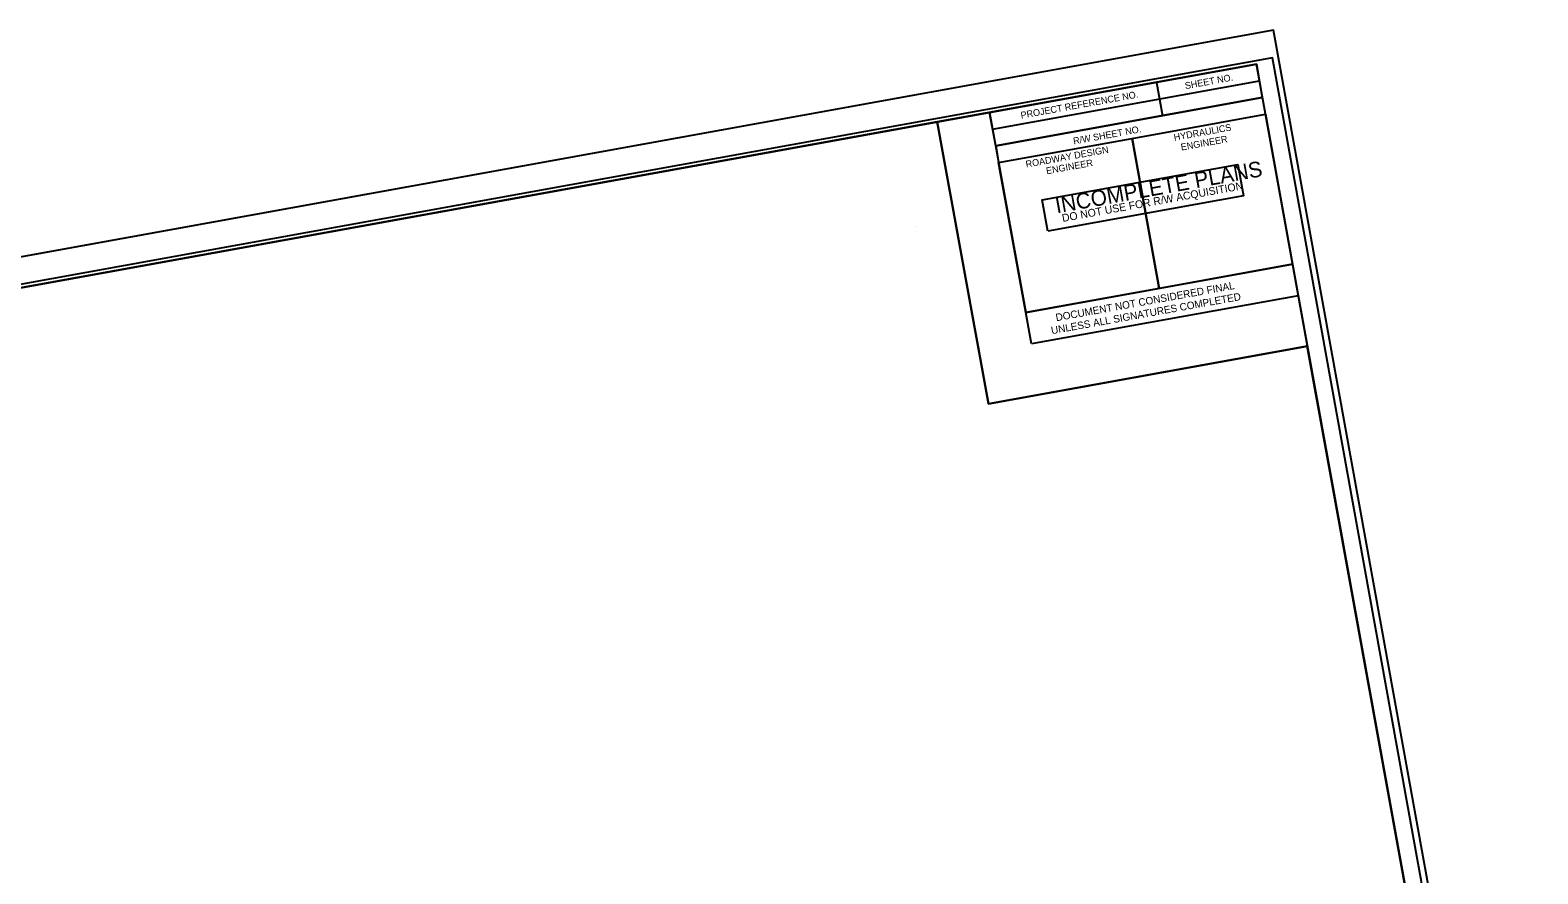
# Model space of a CAD drawing. Extents: x 1617779 to 1622406, y 896496 to 899510.
# Drawn here: x 1620890 to 1622002, y 898422 to 899045 of the extents above; entities that cross this region are included whole.
import ezdxf

# ---------------------------------------------------------------- set-up
doc = ezdxf.new("R2010")
doc.units = 0
for name, color, linetype in [('ControlPoints', 7, 'Continuous'), ('Exist Profile Cell', 7, 'Continuous'), ('Exist Vertical Profile Horizontal Axis Label Major', 7, 'Continuous'), ('Observations', 7, 'Continuous'), ('Prop Horizontal Alignment', 7, 'Continuous'), ('Prop Horizontal Alignment Curve and Spiral Data', 7, 'Continuous'), ('Scratch_Level_4', 7, 'Continuous'), ('Setups', 7, 'Continuous')]:
    doc.layers.add(name, color=color, linetype=linetype)

msp = doc.modelspace()

# ---------------------------------------------------------------- linework, layer by layer
at = {"layer": 'ControlPoints'}
msp.add_lwpolyline([(1620345.8, 897667.3), (1622002.3, 897967.2), (1621807.3, 899044.7), (1620150.7, 898744.8)], close=True, dxfattribs=at)
at = {"layer": 'Exist Profile Cell'}
for p, q in [((1621624.5, 898836.2), (1621821.3, 898871.9)), ((1621624.5, 898836.2), (1621821.3, 898871.9)), ((1621821.3, 898871.9), (1621825.5, 898848.7)), ((1621821.3, 898871.9), (1621825.5, 898848.7)), ((1621825.5, 898848.7), (1621628.7, 898813.1)), ((1621825.5, 898848.7), (1621628.7, 898813.1)), ((1621628.7, 898813.1), (1621624.5, 898836.2)), ((1621628.7, 898813.1), (1621624.5, 898836.2))]:
    msp.add_line(p, q, dxfattribs=at)
at = {"layer": 'Exist Vertical Profile Horizontal Axis Label Major'}
for p, q in [((1621599.9, 898971.5), (1621796.8, 899007.2)), ((1621720.8, 899006.1), (1621725.3, 898981.5)), ((1621602.2, 898959.2), (1621799, 898994.9)), ((1621602.2, 898959.2), (1621799, 898994.9)), ((1621702.9, 898964.7), (1621722.9, 898854.1)), ((1621602.2, 898959.2), (1621604.4, 898946.9))]:
    msp.add_line(p, q, dxfattribs=at)
for points in [[(1621794.6, 899019.5), (1620318.6, 898752.3), (1620505.6, 897719.1), (1621981.6, 897986.3)], [(1621597.7, 898983.9), (1621794.6, 899019.5), (1621799, 898994.9), (1621602.2, 898959.2)], [(1620505.6, 897719.1), (1620318.5, 898752.3), (1621597.7, 898983.9), (1621624.5, 898836.2), (1621821.3, 898871.9), (1621981.6, 897986.3)], [(1621702.9, 898964.7), (1621801.3, 898982.6), (1621821.3, 898871.9), (1621722.9, 898854)], [(1621604.4, 898946.9), (1621702.9, 898964.7), (1621722.9, 898854), (1621624.5, 898836.2)]]:
    msp.add_lwpolyline(points, close=True, dxfattribs=at)
at = {"layer": 'Observations'}
for points in [[(1621596.8, 898768.8), (1621832.3, 898811.4), (1621794.6, 899019.5), (1621559.1, 898976.9)], [(1620318.5, 898752.3), (1620505.6, 897719.1), (1621981.6, 897986.3), (1621832.2, 898811.4), (1621596.8, 898768.8), (1621559.1, 898976.9)]]:
    msp.add_lwpolyline(points, close=True, dxfattribs=at)
at = {"layer": 'Prop Horizontal Alignment'}
msp.add_line((1621807.3, 899044.7), (1620150.7, 898744.8), dxfattribs=at)
at = {"layer": 'Prop Horizontal Alignment Curve and Spiral Data'}
msp.add_lwpolyline([(1621640.6, 898896.3), (1621636.4, 898919.4), (1621781, 898945.6), (1621785.2, 898922.5)], close=True, dxfattribs=at)
at = {"layer": 'Scratch_Level_4'}
msp.add_line((1621543.7, 898900), (1621543.7, 898900), dxfattribs=at)
at = {"layer": 'Setups'}
msp.add_lwpolyline([(1620355, 897689.3), (1621994.3, 897986.1), (1621806.4, 899024.2), (1620167.1, 898727.5)], close=True, dxfattribs=at)

# ---------------------------------------------------------------- texts
at = {"layer": 'Exist Profile Cell'}
for s, p in [('DOCUMENT NOT CONSIDERED FINAL', (1621647, 898829.8)), ('DOCUMENT NOT CONSIDERED FINAL', (1621647, 898829.8)), ('UNLESS ALL SIGNATURES COMPLETED', (1621643.6, 898820.2)), ('UNLESS ALL SIGNATURES COMPLETED', (1621643.6, 898820.2))]:
    msp.add_text(s, height=5.5, rotation=10.2599, dxfattribs=at).set_placement(p)
at = {"layer": 'Exist Vertical Profile Horizontal Axis Label Major'}
for s, p in [('SHEET NO.', (1621742.3, 899001.1)), ('PROJECT REFERENCE NO.', (1621621.1, 898979.3)), ('R/W SHEET NO.', (1621659.9, 898960.3)), ('HYDRAULICS', (1621734.1, 898963)), ('ENGINEER', (1621739.3, 898955.8)), ('ROADWAY DESIGN', (1621624.8, 898943.2)), ('ENGINEER', (1621639.9, 898938.3))]:
    msp.add_text(s, height=5, rotation=10.26, dxfattribs=at).set_placement(p)
at = {"layer": 'Prop Horizontal Alignment Curve and Spiral Data'}
for s, height, p in [('INCOMPLETE PLANS', 11.52, (1621647.3, 898909.4)), ('DO NOT USE FOR R/W ACQUISITION', 5.76, (1621651.7, 898903.1))]:
    msp.add_text(s, height=height, rotation=10.2599, dxfattribs=at).set_placement(p)

doc.saveas('drawing.dxf')
